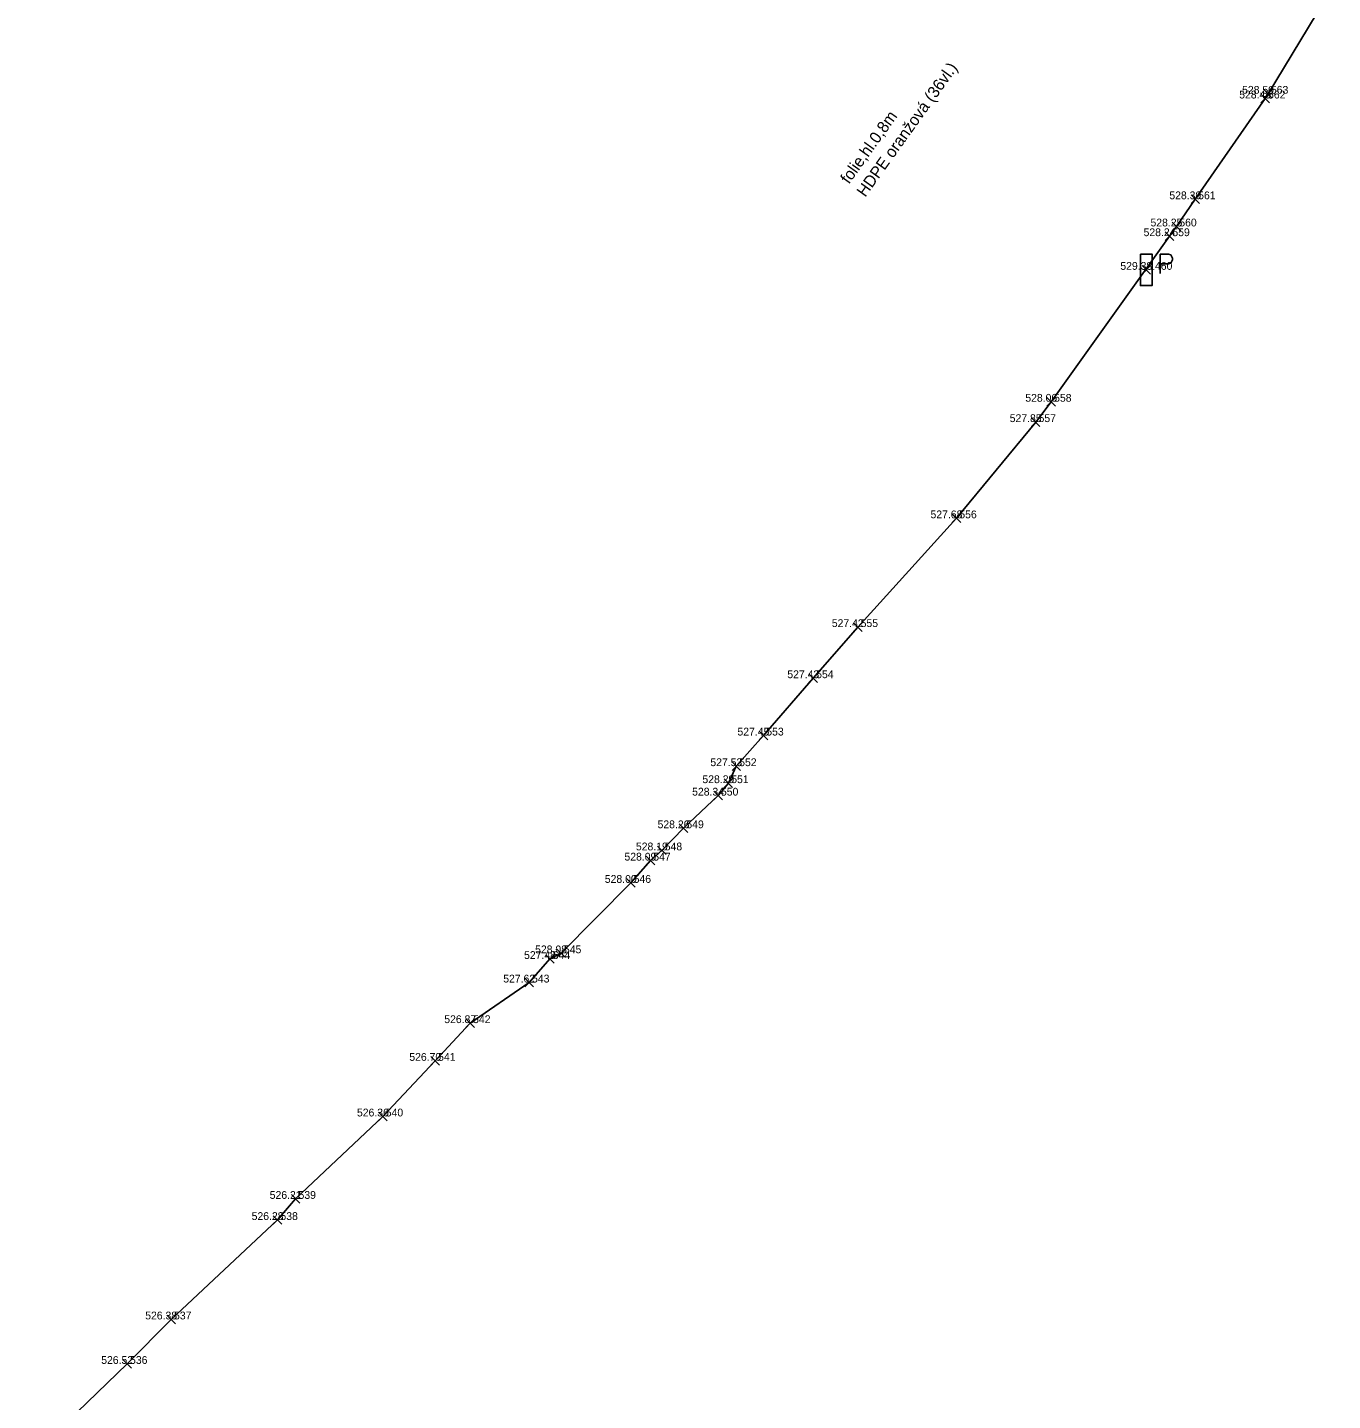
# Model space of a CAD drawing. Extents: x -867433 to -866047, y -1050036 to -1039028.
# Drawn here: x -866287.3 to -866119.7, y -1046070.7 to -1045894.4 of the extents above; entities that cross this region are included whole.
import ezdxf

# ---------------------------------------------------------------- set-up
doc = ezdxf.new("R2010")
doc.units = 0
for name, color, linetype in [('Vrstva 32', 7, 'Continuous'), ('Vrstva 33', 7, 'Continuous'), ('Vrstva 4', 7, 'Continuous'), ('Vrstva 60', 7, 'Continuous'), ('Vrstva 61', 7, 'Continuous')]:
    doc.layers.add(name, color=color, linetype=linetype)

msp = doc.modelspace()

# ---------------------------------------------------------------- linework, layer by layer
at = {"layer": 'Vrstva 32'}
for points in [[(-866119.73, -1045889.26), (-866128.01, -1045902.94), (-866128.38, -1045903.55), (-866137.35, -1045916.48), (-866139.77, -1045919.97), (-866140.66, -1045921.22), (-866155.84, -1045942.47), (-866157.84, -1045945.08), (-866168.01, -1045957.43), (-866180.68, -1045971.39), (-866186.39, -1045977.95), (-866192.79, -1045985.31), (-866196.27, -1045989.24), (-866197.29, -1045991.42), (-866198.61, -1045993.02), (-866203.05, -1045997.21), (-866205.83, -1046000.05), (-866207.3, -1046001.36), (-866209.82, -1046004.22), (-866218.77, -1046013.26), (-866220.19, -1046013.99), (-866222.86, -1046017.01), (-866230.43, -1046022.22)], [(-866168.6, -1045956.83), (-866168.01, -1045957.43)], [(-866168.6, -1045956.83), (-866168.01, -1045957.43)], [(-866230.43, -1046022.22), (-866234.92, -1046027.06), (-866241.64, -1046034.2), (-866252.84, -1046044.78), (-866255.16, -1046047.49), (-866268.82, -1046060.25), (-866274.47, -1046065.96), (-866287.27, -1046078.31)]]:
    msp.add_lwpolyline(points, dxfattribs=at)
at = {"layer": 'Vrstva 33'}
msp.add_lwpolyline([(-866144.39, -1045923.53), (-866142.9, -1045923.53), (-866142.9, -1045927.56), (-866144.39, -1045927.56)], close=True, dxfattribs=at)
for points in [[(-866141.85, -1045926.03), (-866141.85, -1045923.52)], [(-866141.85, -1045923.52), (-866140.81, -1045923.52)], [(-866140.81, -1045924.76), (-866141.85, -1045924.76)], [(-866140.81, -1045923.52), (-866140.49, -1045923.62), (-866140.27, -1045924.03), (-866140.27, -1045924.25), (-866140.49, -1045924.67), (-866140.81, -1045924.76)]]:
    msp.add_lwpolyline(points, dxfattribs=at)
at = {"layer": 'Vrstva 60'}
for p, q in [((-866128.93, -1045904.1), (-866127.83, -1045903)), ((-866127.83, -1045904.1), (-866128.93, -1045903)), ((-866128.56, -1045903.49), (-866127.46, -1045902.39)), ((-866127.46, -1045903.49), (-866128.56, -1045902.39)), ((-866137.9, -1045917.03), (-866136.8, -1045915.93)), ((-866136.8, -1045917.03), (-866137.9, -1045915.93)), ((-866140.32, -1045920.52), (-866139.22, -1045919.42)), ((-866139.22, -1045920.52), (-866140.32, -1045919.42)), ((-866141.21, -1045921.77), (-866140.11, -1045920.67)), ((-866140.11, -1045921.77), (-866141.21, -1045920.67)), ((-866144.19, -1045926.09), (-866143.09, -1045924.99)), ((-866143.09, -1045926.09), (-866144.19, -1045924.99)), ((-866156.39, -1045943.02), (-866155.29, -1045941.92)), ((-866155.29, -1045943.02), (-866156.39, -1045941.92)), ((-866158.39, -1045945.63), (-866157.29, -1045944.53)), ((-866157.29, -1045945.63), (-866158.39, -1045944.53)), ((-866168.56, -1045957.98), (-866167.46, -1045956.88)), ((-866167.46, -1045957.98), (-866168.56, -1045956.88)), ((-866181.23, -1045971.94), (-866180.13, -1045970.84)), ((-866180.13, -1045971.94), (-866181.23, -1045970.84)), ((-866186.94, -1045978.5), (-866185.84, -1045977.4)), ((-866185.84, -1045978.5), (-866186.94, -1045977.4)), ((-866193.34, -1045985.86), (-866192.24, -1045984.76)), ((-866192.24, -1045985.86), (-866193.34, -1045984.76)), ((-866196.82, -1045989.79), (-866195.72, -1045988.69)), ((-866195.72, -1045989.79), (-866196.82, -1045988.69)), ((-866197.84, -1045991.97), (-866196.74, -1045990.87)), ((-866196.74, -1045991.97), (-866197.84, -1045990.87)), ((-866199.16, -1045993.57), (-866198.06, -1045992.47)), ((-866198.06, -1045993.57), (-866199.16, -1045992.47)), ((-866203.6, -1045997.76), (-866202.5, -1045996.66)), ((-866202.5, -1045997.76), (-866203.6, -1045996.66)), ((-866207.85, -1046001.91), (-866206.75, -1046000.81)), ((-866206.75, -1046001.91), (-866207.85, -1046000.81)), ((-866206.38, -1046000.6), (-866205.28, -1045999.5)), ((-866205.28, -1046000.6), (-866206.38, -1045999.5)), ((-866210.37, -1046004.77), (-866209.27, -1046003.67)), ((-866209.27, -1046004.77), (-866210.37, -1046003.67)), ((-866219.32, -1046013.81), (-866218.22, -1046012.71)), ((-866218.22, -1046013.81), (-866219.32, -1046012.71)), ((-866220.74, -1046014.54), (-866219.64, -1046013.44)), ((-866219.64, -1046014.54), (-866220.74, -1046013.44)), ((-866223.41, -1046017.56), (-866222.31, -1046016.46)), ((-866222.31, -1046017.56), (-866223.41, -1046016.46)), ((-866230.98, -1046022.77), (-866229.88, -1046021.67)), ((-866229.88, -1046022.77), (-866230.98, -1046021.67)), ((-866235.47, -1046027.61), (-866234.37, -1046026.51)), ((-866234.37, -1046027.61), (-866235.47, -1046026.51)), ((-866242.19, -1046034.75), (-866241.09, -1046033.65)), ((-866241.09, -1046034.75), (-866242.19, -1046033.65)), ((-866253.39, -1046045.33), (-866252.29, -1046044.23)), ((-866252.29, -1046045.33), (-866253.39, -1046044.23)), ((-866255.71, -1046048.04), (-866254.61, -1046046.94)), ((-866254.61, -1046048.04), (-866255.71, -1046046.94)), ((-866269.37, -1046060.8), (-866268.27, -1046059.7)), ((-866268.27, -1046060.8), (-866269.37, -1046059.7)), ((-866275.02, -1046066.51), (-866273.92, -1046065.41)), ((-866273.92, -1046066.51), (-866275.02, -1046065.41))]:
    msp.add_line(p, q, dxfattribs=at)

# ---------------------------------------------------------------- texts
at = {"layer": 'Vrstva 32'}
msp.add_text('HDPE oranžová (36vl.)', height=1.5, rotation=54.4647, dxfattribs=at).set_placement((-866179.72, -1045916.3))
at = {"layer": 'Vrstva 4'}
msp.add_text('folie,hl.0,8m', height=1.5, rotation=54.4647, dxfattribs=at).set_placement((-866181.81, -1045914.62))
at = {"layer": 'Vrstva 60'}
for s, p in [(' 563', (-866128.01, -1045902.94)), (' 562', (-866128.38, -1045903.55)), (' 561', (-866137.35, -1045916.48)), (' 560', (-866139.77, -1045919.97)), (' 559', (-866140.66, -1045921.22)), (' 1460', (-866143.64, -1045925.54)), (' 558', (-866155.84, -1045942.47)), (' 557', (-866157.84, -1045945.08)), (' 556', (-866168.01, -1045957.43)), (' 555', (-866180.68, -1045971.39)), (' 554', (-866186.39, -1045977.95)), (' 553', (-866192.79, -1045985.31)), (' 552', (-866196.27, -1045989.24)), (' 550', (-866198.61, -1045993.02)), (' 551', (-866197.29, -1045991.42)), (' 549', (-866203.05, -1045997.21)), (' 548', (-866205.83, -1046000.05)), (' 547', (-866207.3, -1046001.36)), (' 546', (-866209.82, -1046004.22)), (' 544', (-866220.19, -1046013.99)), (' 545', (-866218.77, -1046013.26)), (' 543', (-866222.86, -1046017.01)), (' 542', (-866230.43, -1046022.22)), (' 541', (-866234.92, -1046027.06)), (' 540', (-866241.64, -1046034.2)), (' 539', (-866252.84, -1046044.78)), (' 538', (-866255.16, -1046047.49)), (' 537', (-866268.82, -1046060.25)), (' 536', (-866274.47, -1046065.96))]:
    msp.add_text(s, height=1, dxfattribs=at).set_placement(p)
at = {"layer": 'Vrstva 61'}
for s, p in [('528.50 ', (-866131.34, -1045902.94)), ('528.49 ', (-866131.71, -1045903.55)), ('528.30 ', (-866140.68, -1045916.48)), ('528.25 ', (-866143.1, -1045919.97)), ('528.24 ', (-866143.99, -1045921.22)), ('529.38 ', (-866146.97, -1045925.54)), ('528.06 ', (-866159.17, -1045942.47)), ('527.85 ', (-866161.17, -1045945.08)), ('527.68 ', (-866171.34, -1045957.43)), ('527.42 ', (-866184.01, -1045971.39)), ('527.43 ', (-866189.72, -1045977.95)), ('527.45 ', (-866196.12, -1045985.31)), ('527.53 ', (-866199.6, -1045989.24)), ('528.34 ', (-866201.94, -1045993.02)), ('528.29 ', (-866200.62, -1045991.42)), ('528.26 ', (-866206.38, -1045997.21)), ('528.19 ', (-866209.16, -1046000.05)), ('528.09 ', (-866210.63, -1046001.36)), ('528.00 ', (-866213.15, -1046004.22)), ('527.48 ', (-866223.52, -1046013.99)), ('528.08 ', (-866222.1, -1046013.26)), ('527.62 ', (-866226.19, -1046017.01)), ('526.87 ', (-866233.76, -1046022.22)), ('526.70 ', (-866238.25, -1046027.06)), ('526.36 ', (-866244.97, -1046034.2)), ('526.21 ', (-866256.17, -1046044.78)), ('526.28 ', (-866258.49, -1046047.49)), ('526.38 ', (-866272.15, -1046060.25)), ('526.52 ', (-866277.8, -1046065.96))]:
    msp.add_text(s, height=1, dxfattribs=at).set_placement(p)

doc.saveas('drawing.dxf')
